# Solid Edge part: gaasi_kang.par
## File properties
Author: Blackblade
Template: Normal.par
Last saved by: Blackblade
Revision: 3
Application: Solid Edge
Accuracy: 0.990
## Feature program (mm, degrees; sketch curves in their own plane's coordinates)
sketch for "unnamed Protrusion 1" plane through (0, 0, 0) normal (0, 0, 1) x-axis (1, 0, 0)
  line (2, -2.5) -> (-2, -2.5)
  line (-2, -2.5) -> (-2, 0)
  line (-2, 0) -> (-2, 2.5)
  line (-2, 2.5) -> (2, 2.5)
  line (2, 2.5) -> (2, -2.5)
extrude "unnamed Protrusion 1" add finite 2 along +normal
chamfer "Chamfer_1" setback 1
sketch for "ExtrudedCutout_3" plane through (0, 0, 0) normal (1, 0, 0) x-axis (0, 1, 0)
  line (-1.496, 2.0097) -> (-1.996, 1.5097)
  line (-1.996, 1.5097) -> (-1.496, 1.0097)
  line (-1.496, 1.0097) -> (1.504, 1.0097)
  line (1.504, 1.0097) -> (2.004, 1.5097)
  line (2.004, 1.5097) -> (1.504, 2.0097)
  line (1.504, 2.0097) -> (-1.496, 2.0097)
extrude "ExtrudedCutout_3" cut finite 1 symmetric
sketch for "ExtrudedProtrusion_2" plane through (0, 0.004, 1.0097) normal (0, 0, 1) x-axis (1, 0, 0)
  line (-0.5, -0.004) -> (-0.5, 0.496)
  line (-0.5, 0.496) -> (0.5, 0.496)
  line (0.5, 0.496) -> (0.5, -0.504)
  line (0.5, -0.504) -> (-0.5, -0.504)
  line (-0.5, -0.504) -> (-0.5, -0.004)
extrude "ExtrudedProtrusion_2" add finite 4 along +normal
sketch for "ExtrudedProtrusion_3" plane through (0, 0, 0) normal (1, 0, 0) x-axis (0, 1, 0)
  circle centre (0, 5.0097) radius 0.5
extrude "ExtrudedProtrusion_3" add finite 4 symmetric
fillet "Round_1" radius 0.5
fillet "Round_3" radius 1
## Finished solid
Body 1: solid body, 26 faces, 60 edges, 36 vertices.
  Faces by surface: plane 21, cylinder 3, sphere 2
  Edges by curve: line 52, circle 4, ellipse 4
Bounding box of the edges (mm; curved faces can reach further): 4.000 x 5.000 x 5.510, from (-2, -2.5, 0) to (2, 2.5, 5.5097).
Cylindrical faces by radius (mm): R0.5 x1, R1 x2
Spherical faces by radius (mm): R0.5 x2
Planar faces by outward normal: +x 4, +y 2, +z 4, -x 4, -y 2, -z 1, oblique 4
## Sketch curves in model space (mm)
circle centre (0, 0, 5.0097) radius 0.5
circle centre (0, 0, 5.0097) radius 0.5
line (-0.5, 0.5, 1.0097) -> (0.5, 0.5, 1.0097)
line (0.5, 0.5, 1.0097) -> (0.5, -0.5, 1.0097)
line (0.5, -0.5, 1.0097) -> (-0.5, -0.5, 1.0097)
line (-0.5, -0.5, 1.0097) -> (-0.5, 0, 1.0097)
line (-0.5, 0, 1.0097) -> (-0.5, 0.5, 1.0097)
line (0, 1.504, 1.0097) -> (0, 2.004, 1.5097)
line (0, 2.004, 1.5097) -> (0, 1.504, 2.0097)
line (0, 1.504, 2.0097) -> (0, -1.496, 2.0097)
line (0, -1.496, 2.0097) -> (0, -1.996, 1.5097)
line (0, -1.996, 1.5097) -> (0, -1.496, 1.0097)
line (0, -1.496, 1.0097) -> (0, 1.504, 1.0097)
line (-2, 2.5, 0) -> (2, 2.5, 0)
line (2, 2.5, 0) -> (2, -2.5, 0)
line (2, -2.5, 0) -> (-2, -2.5, 0)
line (-2, -2.5, 0) -> (-2, 0, 0)
line (-2, 0, 0) -> (-2, 2.5, 0)
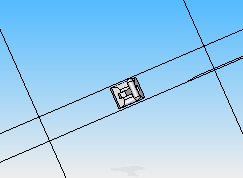
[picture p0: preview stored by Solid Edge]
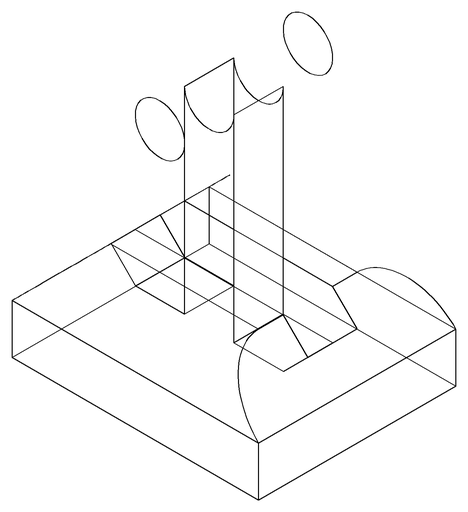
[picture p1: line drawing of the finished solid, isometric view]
